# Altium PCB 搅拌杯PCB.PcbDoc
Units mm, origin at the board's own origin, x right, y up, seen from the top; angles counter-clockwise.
Board outline 36 x 32.5 mm, 2 copper layers (Top Layer, Bottom Layer); 74 components, 45 nets, 191 pads, 40 vias.
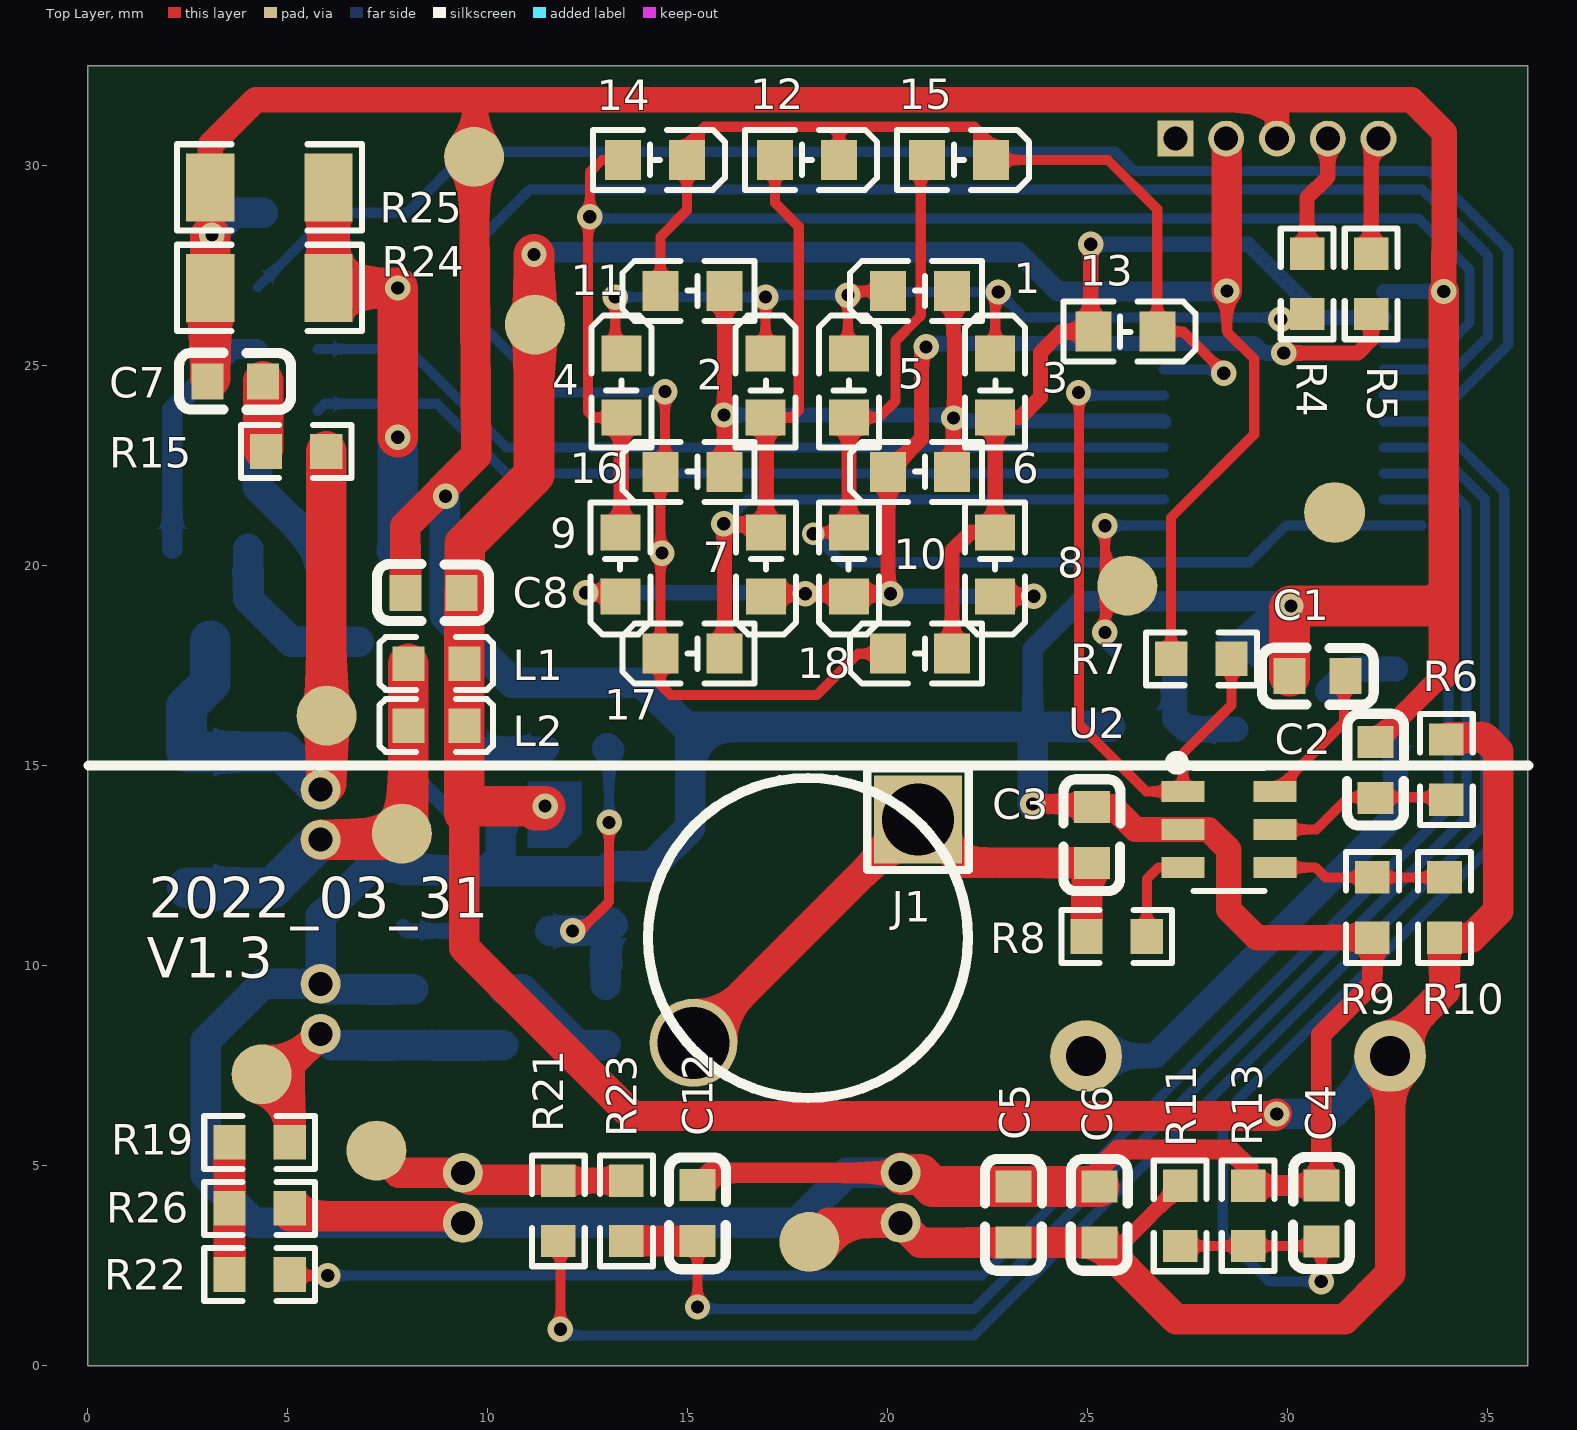
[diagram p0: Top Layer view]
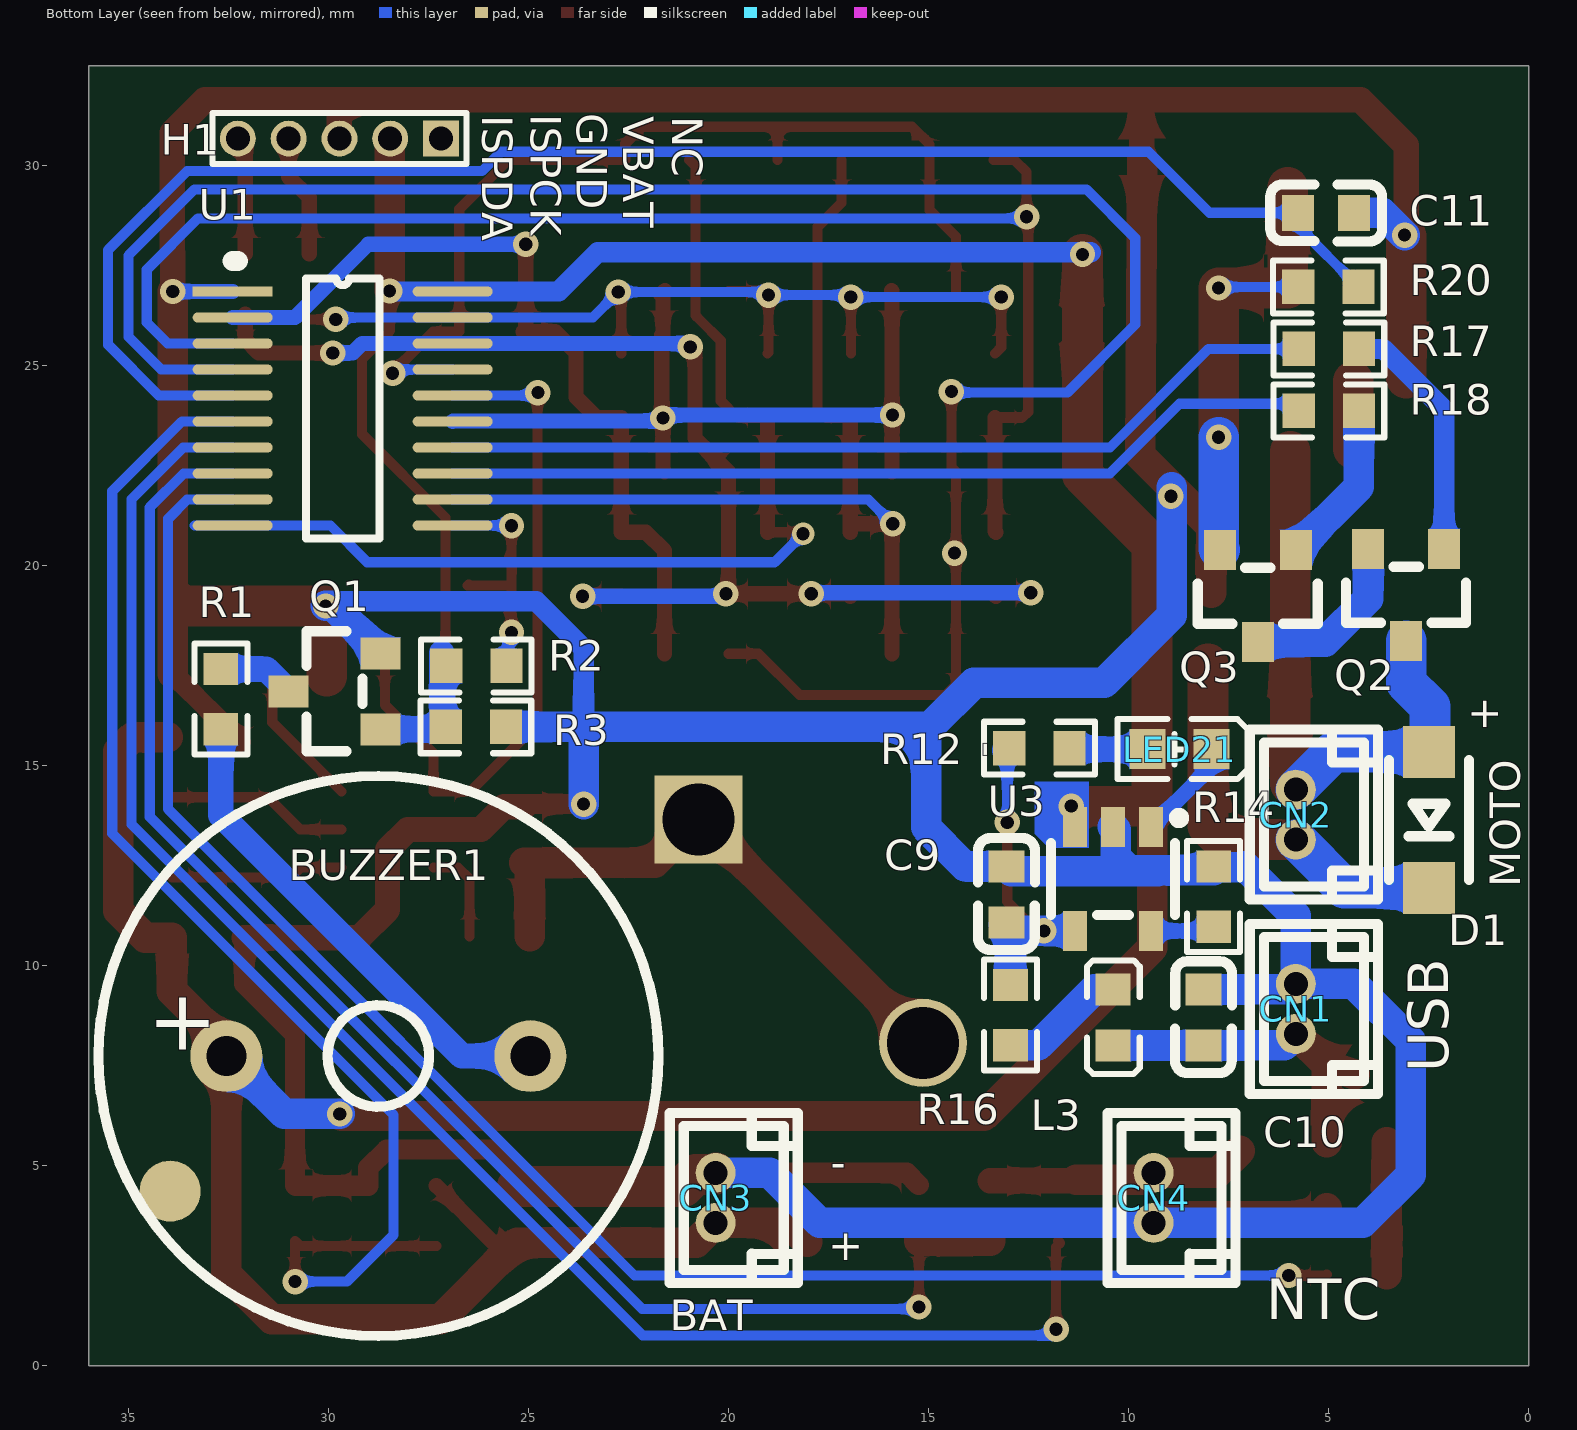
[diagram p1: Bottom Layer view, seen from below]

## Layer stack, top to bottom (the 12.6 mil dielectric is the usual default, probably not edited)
Top Solder: solder mask 0.0102, Solder Resist, Dk 3.5
Top Layer: signal copper 0.0356
Dielectric 1: dielectric 0.32, FR-4, Dk 4.8
Bottom Layer: signal copper 0.0356
Bottom Solder: solder mask 0.0102, Solder Resist, Dk 3.5

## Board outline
0,0 0,32.5 36,32.5 36,0

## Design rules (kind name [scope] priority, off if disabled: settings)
Clearance [All] p1: gap=0.203
ComponentClearance [All] p1 off: gap=0.254 collisioncheckmode=3 verticalgap=0.254 showdistances=FALSE
PolygonConnect [All] p1: connectstyle=Relief reliefconductorwidth=0.254 reliefentries=4 polygonreliefangle="90 Angle" airgapwidth=0.254
RoutingVias [All] p1: holewidth=0.711 width=1.27 viastyle="Through Hole" minholewidth=0.254 minwidth=0.254 maxholewidth=0.711 maxwidth=1.27
SolderMaskExpansion [All] p1: expansion=0.102
Width [All] p1: maxlimit=1.27 minlimit=0.203 preferedwidth=0.254
29 further rules are at their usual default settings.

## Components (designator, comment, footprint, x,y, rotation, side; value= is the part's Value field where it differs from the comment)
1 "LED-0603_W" LED0603-FD_WHITE 20.803,26.873 r180 top (schematic designator LED1)
2 "LED-0603_W" LED0603-FD_WHITE 16.942,24.511 r90 top (schematic designator LED2)
3 "LED-0603_W" LED0603-FD_WHITE 22.682,24.511 r90 top (schematic designator LED3)
4 "LED-0603_W" LED0603-FD_WHITE 13.335,24.511 r90 top (schematic designator LED4)
5 "LED-0603_W" LED0603-FD_WHITE 19.025,24.511 r90 top (schematic designator LED5)
6 "LED-0603_W" LED0603-FD_WHITE 20.803,22.352 r180 top (schematic designator LED6)
7 "LED-0603_W" LED0603-FD_WHITE 16.955,20.041 r270 top (schematic designator LED7)
8 "LED-0603_W" LED0603-FD_WHITE 22.682,20.041 r270 top (schematic designator LED8)
9 "LED-0603_W" LED0603-FD_WHITE 13.31,20.041 r270 top (schematic designator LED9)
10 "LED-0603_W" LED0603-FD_WHITE 19.025,20.041 r270 top (schematic designator LED10)
11 "LED-0603_W" LED0603-FD_WHITE 15.113,26.873 r180 top (schematic designator LED11)
12 "LED-0603_W" LED0603-FD_WHITE 17.977,30.15 r0 top (schematic designator LED12)
13 "LED-0603_W" LED0603-FD_WHITE 25.933,25.857 r0 top (schematic designator LED13)
14 "LED-0603_W" LED0603-FD_WHITE 14.173,30.15 r0 top (schematic designator LED14)
15 "LED-0603_W" LED0603-FD_WHITE 21.781,30.15 r0 top (schematic designator LED15)
16 "LED-0603_W" LED0603-FD_WHITE 15.113,22.352 r180 top (schematic designator LED16)
17 "LED-0603_W" LED0603-FD_WHITE 15.113,17.805 r180 top (schematic designator LED17)
18 "LED-0603_W" LED0603-FD_WHITE 20.803,17.805 r180 top (schematic designator LED18)
BUZZER1 "FMQ-BUZZER2" BUZ-TH_BD12.0-P7.60-D0.6-FD 28.753,7.747 r180 bottom
C1 "4.7nF" C0603 30.74,17.245 r180 top
C2 "0.1u" C0603 32.188,14.898 r270 top
C3 "nc" C0603 25.101,13.276 r90 top
C4 "0.1u" C0603 30.836,3.816 r270 top
C5 "1uF" C0603 23.139,3.785 r90 top
C6 "0.1u" C0603 25.286,3.785 r90 top
C7 "0.1u" C0603 3.683,24.613 r0 top
C8 "10uF" C0603 8.636,19.329 r0 top
C9 "4.7uF" C0603 13.056,11.791 r270 bottom
C10 "10uF" C0603 8.128,8.712 r270 bottom
C11 "0.1u" C0603 5.066,28.829 r0 bottom
C12 "0.1u" C0603 15.24,3.821 r90 top
CN1 "0530470210" CONN-TH_0530470210 5.817,8.925 r90 bottom
CN2 "0530470210" CONN-TH_0530470210 5.817,13.782 r90 bottom
CN3 "0530470210" CONN-TH_0530470210 20.32,4.201 r90 bottom
CN4 "0530470210" CONN-TH_0530470210 9.373,4.201 r90 bottom
D1 "1N4148W" SOD-123FL_L2.6-W1.6-LS3.4-RD 2.489,13.648 r270 bottom
H1 "HDR-F-2.54_1x5" 1.27mm_5PIN 27.187,30.683 r0 bottom
J1 "HDR-M-2.54_1x1" HDR-M-2.54_1X1 20.752,13.665 r0 top
L1 "22uH" L0603 8.712,17.551 r0 top
L2 "22uH" L0603 8.712,16.001 r0 top
L3 "BEAD" L0603 10.389,8.712 r270 bottom
LED21 "LED-0603_W" LED0603-FD_WHITE 8.725,15.418 r180 bottom
Q1 "2N7002" SOT-23_L2.9-W1.3-P0.95-LS2.4-BR 29.847,16.866 r180 bottom
Q2 "2N7002" SOT-23_L2.9-W1.3-P0.95-LS2.4-BR 3.059,19.279 r90 bottom
Q3 "2N7002" SOT-23_L2.9-W1.3-P0.95-LS2.4-BR 6.767,19.253 r90 bottom
R1 "50R" R0603 32.69,16.671 r90 bottom
R2 "1K" R0603 26.306,17.501 r180 bottom
R3 "100K" R0603 26.316,15.977 r180 bottom
R4 "100R" R0603 30.48,27.051 r270 top
R5 "100R" R0603 32.08,27.051 r270 top
R6 "0R" R0603 33.96,14.91 r90 top
R7 "10K" R0603 27.838,17.678 r180 top
R8 "1K" R0603 25.72,10.736 r180 top
R9 "NC" R0603 32.112,11.461 r90 top
R10 "NC" R0603 33.915,11.461 r90 top
R11 "3M" R0603 27.305,3.751 r90 top
R12 "1k" R0603 12.226,15.443 r180 bottom
R13 "1M" R0603 29.007,3.754 r270 top
R14 "1k" R0603 7.874,11.735 r90 bottom
R15 "1k" R0603 5.207,22.86 r0 top
R16 "0R" R0603 12.95,8.772 r270 bottom
R17 "100R" R0603 4.992,25.425 r180 bottom
R18 "100R" R0603 4.992,23.876 r180 bottom
R19 "1k" R0603 4.293,5.588 r0 top
R20 "1k" R0603 5.004,26.975 r180 bottom
R21 "200K" R0603 11.76,3.877 r90 top
R22 "1k" R0603 4.293,2.286 r0 top
R23 "1k" R0603 13.462,3.877 r270 top
R24 "1R" R1206 4.538,26.949 r0 top
R25 "1R" R1206 4.538,29.464 r0 top
R26 "100K" R0603 4.293,3.937 r0 top
U1 "ES7P0693FHTF" TSOP20 32.395,26.862 r180 bottom
U2 "AS01C(AI01)" SOT-23-6_L2.9-W1.6-P0.95-LS2.8-BL 28.527,13.411 r270 top
U3 "HE4054B" SOT-23-5_L3.0-W1.7-P0.95-LS2.8-BR 10.389,12.175 r90 bottom

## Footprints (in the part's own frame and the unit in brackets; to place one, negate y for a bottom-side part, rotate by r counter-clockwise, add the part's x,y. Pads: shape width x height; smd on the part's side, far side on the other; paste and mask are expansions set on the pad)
1.27mm_5PIN [mm]
  rect 0.9x0.9 hole 0.6: 1(0,0)
  round 0.9 hole 0.6: 2(1.27,0) 3(2.54,0) 4(3.81,0) 5(5.08,0)
  silkscreen extent -0.64,-0.64 5.71,0.64
BUZ-TH_BD12.0-P7.60-D0.6-FD [mm]
  round 1.8 hole 1: 1(-3.8,0) 2(3.8,0)
  silkscreen extent -7,-7 7,7
C0603 [mm]
  rect 0.8x0.9 smd: 1(-0.7,0) 2(0.7,0)
  silkscreen extent -1.41,-0.71 1.39,0.72
CONN-TH_0530470210 [mm]
  round 1 hole 0.6: 1(-0.625,0) 2(0.625,0)
  silkscreen extent -2.13,-2.05 2.13,1.15
HDR-M-2.54_1X1 [mm]
  rect 2.2x2.2 hole 1.8: 1(0,0)
  silkscreen extent -1.27,-1.27 1.27,1.27
L0603 [mm]
  rect 0.8x0.864 smd: 1(-0.7,0) 2(0.7,0)
  silkscreen extent -1.42,-0.65 1.41,0.67
LED0603-FD_WHITE [mm]
  rect 0.9x1 smd: 1(-0.8,0) 2(0.8,0)
  silkscreen extent -1.55,-0.75 1.75,0.75
R0603 [mm]
  rect 0.806x0.864 smd: 1(-0.753,0) 2(0.753,0)
  silkscreen extent -1.39,-0.66 1.39,0.66
R1206 [mm]
  rect 1.208x1.701 smd: 1(-1.479,0) 2(1.479,0)
  silkscreen extent -2.31,-1.08 2.31,1.08
SOD-123FL_L2.6-W1.6-LS3.4-RD [mm]
  rect 1.3x1.3 smd: 1(1.7,0) 2(-1.7,0)
  silkscreen extent -1.5,-1 1.5,1
SOT-23-5_L3.0-W1.7-P0.95-LS2.8-BR [mm]
  rect 1x0.6 smd: 1(1.3,-0.95) 2(1.3,0) 3(1.3,0.95) 4(-1.3,0.95) 5(-1.3,-0.95)
  silkscreen extent -0.9,-1.78 1.65,1.55
SOT-23-6_L2.9-W1.6-P0.95-LS2.8-BL [mm]
  rect 0.532x1.072 smd: 1(-0.95,-1.149) 2(0,-1.149) 3(0.95,-1.149) 4(0.95,1.149) 5(0,1.149) 6(-0.95,1.149)
  silkscreen extent -1.82,-1.45 1.54,0.89
SOT-23_L2.9-W1.3-P0.95-LS2.4-BR [mm]
  rect 1x0.8 smd: 1(1.15,-0.95) 2(1.15,0.95) 3(-1.15,0)
  silkscreen extent -0.7,-1.5 0.7,1.5
TSOP20 [mm]
  rect 2x0.25 smd: 1(0,0)
  oval 2x0.25 smd: 2(0,-0.65) 3(0,-1.3) 4(0,-1.95) 5(0,-2.6) 6(0,-3.25) 7(0,-3.9) 8(0,-4.55) 9(0,-5.2) 10(0,-5.85) 11(5.5,-5.85) 12(5.5,-5.2) 13(5.5,-4.55) 14(5.5,-3.9) 15(5.5,-3.25) 16(5.5,-2.6) 17(5.5,-1.95) 18(5.5,-1.3) 19(5.5,-0.65) 20(5.5,0)
  silkscreen extent 0,-6.18 3.66,0.76

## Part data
L3: library part 22uH
R1: library part 100R
R3: library part 1K
R6 R7 R16: library part NC
R11: library part 430k
R13: library part 430K
R21 R26: library part 33K

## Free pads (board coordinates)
  round 2.2 hole 1.8: 0(15.138,8.077)
  round 1.5 smd: 2(4.343,7.29) 2(5.969,16.256) 2(7.214,5.385) 2(7.849,13.31) 2(9.652,30.226) 2(11.176,26.035) 2(18.034,3.099) 2(25.984,19.507)
  round 1.524 smd: 3(31.166,21.336)
  round 2.54 on Top Solder: 3(31.166,21.336)
  round 1.524 smd far side: 3(33.96,4.369)
  round 2.54 on Bottom Solder: 3(33.96,4.369)

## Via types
v1: diameter 0.635, hole 0.33, Top Layer to Bottom Layer, tented both sides, 39 vias
v2: diameter 0.559, hole 0.33, Top Layer to Bottom Layer, 1 vias

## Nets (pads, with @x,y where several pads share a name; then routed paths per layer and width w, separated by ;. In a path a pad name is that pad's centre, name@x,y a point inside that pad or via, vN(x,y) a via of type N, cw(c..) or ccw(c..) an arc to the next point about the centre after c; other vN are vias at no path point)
BUZZER: pad.2@25.984,19.507 R2.2 U1.11 | length 5.9
  Top Layer w0.254: v1(25.425,18.339) pad.2@25.425,19.482 ; v1(25.425,21.006) pad.2@25.425,19.482 ; pad.2@26.492,19.533 26.518,19.507 25.984,19.507 25.451,19.507 pad.2@25.425,19.482
  Bottom Layer w0.254: v1(25.425,18.339) 25.425,18.07 R2.2@25.664,17.831 ; v1(25.425,21.006) 25.431,21.011 U1.11
GND: C1.2 C2.1 C3.2 C4.1 C5.2 C6.2 C7.1 C8.1 C9.1 C10.1 C11.1 C12.2 CN1.2 CN3.2 CN4.1 H1.3 pad.2@9.652,30.226 Q1.2 R3.2 R9.1 R13.1 R14.2 R24.1 R25.1 R26.2 U1.1 U2.2 U3.2 | length 192.5
  Top Layer w0.508: C12.2 15.545,4.826 CN3.2 ; v1(23.622,14.046) 25.031,14.046 C3.2 ; C6.2 25.286,4.94 25.756,5.41 28.55,5.41 29.007,4.953 R13.1 30.827,4.507 C4.1 30.836,8.28 32.112,9.556 R9.1 ; C2.1 33.895,17.306
  Top Layer w0.635: C7.1 C7.1@3.059,24.689 ; v1@3.059,28.27 R25.1 3.059,30.516 4.197,31.654 9.693,31.654 ; pad.2@9.652,30.226 9.693,31.591 9.693,31.598 9.693,31.654 ; C3.2 25.622,13.976 26.187,13.411 U2.2 28.016,13.411 28.524,12.903 28.524,11.405 29.221,10.708 R9.1 ; H1.3@29.727,30.836 29.727,31.267 29.34,31.654 ; 33.909,27.661 33.909,30.836 33.091,31.654 29.34,31.654 ; 9.693,31.654 29.34,31.654
  Top Layer w0.762: R26.2 5.046,3.742 9.092,3.742 9.258,3.576 CN4.1 ; C8.1 7.936,20.992 9.703,22.758 pad.2@9.652,30.226 ; 33.757,19.101 33.895,19.101 ; 33.895,17.306 33.895,19.101 ; v1(33.895,26.862) 33.895,19.101
  Top Layer w1.016: C7.1@3.059,24.689 R24.1 v1@3.059,28.245 ; CN3.2 20.359,4.787 20.822,4.787 21.124,4.485 C6.2 ; C1.2 30.04,18.966 v1(30.074,18.999) 33.655,18.999 33.757,19.101
  Bottom Layer w0.381: U1.1 v1(33.895,26.862)
  Bottom Layer w0.508: 23.622,16.104 23.622,17.932 24.803,19.113 29.959,19.113 v1(30.074,18.999)
  Bottom Layer w0.762: v1(3.099,28.27) 3.658,28.829 C11.1 ; R14.2 R14.2@7.874,12.471 ; C10.1 5.955,9.412 CN1.2 ; v1@8.915,21.971 8.915,18.771 10.612,17.074 13.863,17.074 14.96,15.977 15.062,15.977 ; 9.267,12.37 12.935,12.37 C9.1 14.091,12.49 15.062,13.462 15.062,15.977 ; U3.2 10.323,13.409 10.323,12.733 9.981,12.391 7.874,12.391 R14.2@7.874,12.471 ; CN3.2 18.974,4.826 17.724,3.576 CN4.1 4.146,3.576 2.946,4.775 2.946,8.128 4.369,9.55 CN1.2 ; v1(23.622,14.046) 23.622,15.977 ; 23.622,16.104 23.749,15.977 ; R3.2 23.749,15.977 ; Q1.2 29.88,18.999 v1(30.074,18.999) ; CN1.2 5.817,11.252 5.842,11.252 7.078,12.488 7.078,12.471 R14.2@7.874,12.471 ; 15.062,15.977 23.622,15.977 ; 23.622,15.977 23.749,15.977
  other v1: 8.941,21.742
IO_OUT: R21.1 U1.7 | length 41.9
  Top Layer w0.254: R21.1 11.709,3.073 11.811,2.971 v1(11.811,0.914)
  Bottom Layer w0.254: v1(11.811,0.914) 11.963,0.762 22.147,0.762 34.925,13.54 34.925,21.666 33.63,22.962 U1.7
ISPCK: H1.4 R4.1 | length 3.2
  Top Layer w0.381: R4.1 30.48,29.21 30.997,29.727 H1.4 H1.4@30.997,30.836
ISPDA: H1.5 R5.1 | length 3.1
  Top Layer w0.381: R5.1 32.08,30.649 H1.5@32.267,30.836
LED_IO_0: 1.2 2.2 3.2 4.2 5.2 R4.2 U1.19 | length 24.9
  Top Layer w0.254: v1(13.183,26.721) 13.183,25.463 4.2 ; 2.2 v1(16.942,26.721) ; 5.2 18.999,25.336 v1(18.999,26.772) 19.101,26.873 1.2 ; 3.2 22.682,26.772 v1(22.758,26.848) ; v1(29.82,26.162) 30.556,26.162 R4.2@30.605,26.212
  Bottom Layer w0.254: v1(13.183,26.721) v1(16.942,26.721) 16.992,26.772 v1(18.999,26.772) 18.923,26.848 v1(22.758,26.848) 23.395,26.212 U1.19 29.77,26.212 v1(29.82,26.162)
LED_IO_1: 6.2 7.2 8.2 9.2 10.2 R5.2 U1.18 | length 32.9
  Top Layer w0.381: v1(12.446,19.329) 13.348,19.329 13.373,19.304 9.2 ; 7.2 17.019,19.304 v1(17.932,19.304) v1@20.003,19.304 ; 6.2 v1@20.003,19.304 ; 6.2@20.041,22.39 20.841,23.19 20.841,25.387 20.879,25.349 20.98,25.451 v1(20.955,25.476) ; v1(20.066,19.304) v1@20.003,19.304 ; 8.2 v1(23.647,19.241) ; v1(29.896,25.324) 31.75,25.324 32.08,25.654 R5.2
  Bottom Layer w0.381: v1(12.446,19.329) 17.907,19.329 v1(17.932,19.304) ; v1(20.066,19.304) 20.129,19.241 v1(23.647,19.241) ; v1@20.913,25.478 20.937,25.502 20.955,25.483 v1(20.955,25.476) 21.04,25.562 U1.18 29.159,25.562 29.397,25.324 v1(29.896,25.324)
LED_IO_2: 11.2 12.2 13.2 14.2 15.2 U1.17 | length 24.5
  Top Layer w0.254: 11.2 14.313,28.232 14.973,28.892 14.2 14.973,30.535 15.418,30.98 18.777,30.98 ; 12.2 18.777,30.98 ; v1(28.397,24.816) 28.397,24.841 27.381,25.857 13.2 26.733,28.918 25.502,30.15 15.2 22.581,30.556 22.157,30.98 18.777,30.98
  Bottom Layer w0.254: U1.17 v1@28.397,24.912
LED_IO_3: 16.2 17.2 18.2 U1.4 | length 52.3
  Top Layer w0.254: v1(14.427,24.359) 14.427,22.466 16.2 17.2 14.313,17.03 14.568,16.775 18.223,16.775 19.253,17.805 18.2
  Bottom Layer w0.254: v1@14.173,24.333 11.532,24.333 9.83,26.035 9.83,28.194 11.049,29.413 33.35,29.413 35,27.763 35,25.729 34.183,24.912 U1.4 ; v1@14.326,20.32 v1(14.351,20.32) v1@14.427,20.396
LED_IO_4: 1.1 6.1 11.1 16.1 U1.15 | length 20.5
  Top Layer w0.381: 16.1 11.1 11.1@15.926,26.886 ; 1.1@21.59,26.886 1.1 21.692,26.784 21.641,26.733 21.641,25.796 21.666,25.771 21.666,23.724 v1(21.641,23.698) ; 6.1 21.641,22.39 v1(21.641,23.698) ; v1@21.641,23.749 v1(21.641,23.698)
  Bottom Layer w0.381: v1(15.9,23.774) v1@21.641,23.774 ; v1(21.641,23.698) v1@21.641,23.774 ; U1.15 26.885,23.622 21.615,23.622 21.565,23.673 21.565,23.698 v1@21.641,23.774
LED_IO_5: 2.1 7.1 12.1 17.1 U1.12 | length 25.6
  Top Layer w0.254: 2.1 17.59,23.711 17.772,23.893 17.772,28.481 17.177,29.077 12.1
  Top Layer w0.381: v1(15.896,21.052) v1@15.913,21.052 ; 17.1 v1@15.913,21.052 ; 7.1@16.744,21.052 v1@15.913,21.052 ; 2.1 16.955,23.697 7.1
  Bottom Layer w0.254: v1(15.896,21.052) 16.505,21.662 U1.12
LED_IO_6: 3.1 8.1 13.1 18.1 U1.2 | length 21
  Top Layer w0.381: 18.1 21.603,20.383 22.06,20.841 8.1 3.1 23.305,23.711 23.812,24.219 23.812,25.336 24.333,25.857 13.1@25.07,25.857 ; v1(25.07,28.042) 13.1@25.07,25.857 ; 13.1 13.1@25.07,25.857
  Bottom Layer w0.381: v1(25.07,28.042) 29.007,28.042 30.837,26.212 U1.2
LED_IO_7: 4.1 9.1 14.1 U1.3 | length 37.1
  Top Layer w0.254: 4.1 12.649,23.711 12.505,23.855 12.505,28.685 v1(12.548,28.727) 12.548,29.845 12.852,30.15 14.1
  Top Layer w0.381: 9.1 13.335,20.866 4.1
  Bottom Layer w0.254: v1@12.446,28.702 12.471,28.727 v1(12.548,28.727) ; v1@12.53,28.778 12.548,28.761 v1(12.548,28.727) ; U1.3 34.02,25.562 34.543,26.085 34.543,27.408 33.261,28.689 12.586,28.689 v1(12.548,28.727)
LED_IO_8: 5.1 10.1 15.1 U1.10 | length 27.3
  Top Layer w0.254: v2(18.136,20.803) 18.174,20.841 10.1 ; 5.1 19.774,23.711 20.193,24.13 20.193,25.63 20.712,26.149 20.714,26.149 20.823,26.258 20.823,29.992 15.1
  Top Layer w0.381: 10.1 5.1
  Bottom Layer w0.254: v2(18.136,20.803) 18.847,20.091 29.032,20.091 29.952,21.011 U1.10 U1.10@33.345,21.011
MOTO_CONTROL_A: R17.1 U1.14 | length 22.2
  Bottom Layer w0.254: R17.1 8.001,25.425 10.465,22.962 U1.14
MOTO_CONTROL_B: R18.1 U1.13 | length 21.9
  Bottom Layer w0.254: R18.1 5.923,24.054 8.726,24.054 10.468,22.312 U1.13
MOTO_CURRERN: C11.2 R20.2 U1.5 | length 39.9
  Bottom Layer w0.254: R20.2 5.766,28.49 C11.2 7.976,28.829 9.5,30.353 25.679,30.353 26.162,29.87 33.54,29.87 35.509,27.901 35.509,25.527 34.244,24.262 U1.5
NetBUZZER1_2: BUZZER1.2 R1.1 | length 12.4
  Bottom Layer w0.635: BUZZER1.2 26.67,7.747 32.69,13.767 R1.1
NetC1_1: C1.1 U2.6 | length 3.6
  Top Layer w0.254: U2.6 31.408,16.093 31.408,17.245 C1.1
NetC2_2: C2.2 R6.1 U2.5 | length 4.7
  Top Layer w0.254: U2.5 30.709,13.411 31.514,14.216 R6.1@34.017,14.216
NetC3_1: C3.1 J1.1 pad.0 R8.2 | length 14.6
  Top Layer w0.762: pad.0 J1.1@20.726,13.665 ; J1.1 21.841,12.576 C3.1 24.966,12.442 R8.2
NetC7_2: C7.2 R15.1 | length 1.8
  Top Layer w0.762: R15.1@4.383,22.931 R15.1
  Top Layer w1.016: R15.1@4.383,22.931 C7.2
NetC9_2: C9.2 R12.1 R16.1 U3.4 | length 8.4
  Top Layer w0.254: v1(12.116,10.875) 12.298,10.875 13.03,11.608 v1(13.03,13.589)
  Bottom Layer w0.254: v1(13.03,13.589) R12.1@13.03,15.392
  Bottom Layer w0.762: U3.4@11.557,10.875 v1(12.116,10.875) 12.84,10.875 C9.2@12.95,10.985 ; R16.1 C9.2@12.95,10.985 ; R12.1 R12.1@13.03,15.392 ; C9.2@12.95,10.985 C9.2@12.989,11.024 ; C9.2@12.989,11.024 13.123,11.024 C9.2 C9.2@12.989,11.024
NetCN2_1: CN2.1 D1.1 L1.1 L2.1 pad.2@7.849,13.31 | length 10.2
  Top Layer w1.016: CN2.1 7.671,13.157 8.012,13.499 L2.1 L1.1
  Bottom Layer w1.016: D1.1 4.608,11.948 CN2.1
NetCN2_2: CN2.2 D1.2 pad.2@5.969,16.256 Q2.3 R15.2 | length 15.3
  Top Layer w0.762: CN2.2 CN2.2@5.96,14.551
  Top Layer w1.016: CN2.2@5.96,14.551 R15.2
  Bottom Layer w1.016: Q2.3 3.059,17.08 2.464,16.485 2.464,15.374 D1.2 4.876,15.348 CN2.2
NetCN4_2: CN4.2 pad.2@7.214,5.385 R21.2 R23.1 | length 6.6
  Top Layer w0.635: 11.303,4.66 11.333,4.63 R21.2 R23.1
  Top Layer w0.762: pad.2@7.214,5.385 7.772,4.826 CN4.2 9.539,4.66 11.303,4.66
NetL3_1: L3.1 R16.2 | length 3.1
  Bottom Layer w0.762: L3.1 10.857,9.412 12.251,8.019 R16.2
NetLED21_1: LED21.1 R12.2 | length 2
  Bottom Layer w0.635: LED21.1 11.448,15.418 R12.2
NetLED21_2: LED21.2 U3.1 | length 2.6
  Bottom Layer w0.381: LED21.2 7.925,14.989 U3.1
NetQ1_1: Q1.1 R2.1 R3.1 | length 3.3
  Bottom Layer w0.635: R2.1@27.171,17.831 27.171,16.18 27.435,15.916 Q1.1
NetQ1_3: Q1.3 R1.2 | length 1.9
  Bottom Layer w0.635: Q1.3 31.555,17.424 R1.2
NetQ2_1: Q2.1 R17.2 | length 6.2
  Bottom Layer w0.508: Q2.1 2.109,23.902 3.632,25.425 R17.2
NetQ2_2: Q2.2 Q3.3 | length 4.5
  Bottom Layer w0.762: Q2.2 4.009,19.181 5.087,18.103 Q3.3
NetQ3_1: Q3.1 R18.2 | length 4.1
  Bottom Layer w0.762: R18.2 4.239,21.981 Q3.1
NetQ3_2: Q3.2 R20.1 R24.2 R25.2 | length 12.8
  Top Layer w1.016: R25.2 R24.2 v1(7.747,26.949) v1(7.747,23.216)
  Bottom Layer w0.254: R20.1 7.722,26.975 v1(7.747,26.949)
  Bottom Layer w1.016: Q3.2 7.747,20.433 v1(7.747,23.216)
NetR8_1: R8.1 U2.3 | length 2.5
  Top Layer w0.254: R8.1 26.473,12.173 26.761,12.461 U2.3
NetR9_2: R9.2 R10.2 U2.4 | length 4.3
  Top Layer w0.254: U2.4 30.693,12.461 30.941,12.214 R9.2 R10.2
NetR14_1: R14.1 U3.5 | length 1.6
  Bottom Layer w0.381: R14.1 7.98,10.875 U3.5
NetR19_1: R19.1 R22.1 R26.1 | length 3.3
  Top Layer w0.762: R22.1 R26.1 R19.1
NTC_IN: C12.1 R23.2 U1.8 | length 38.1
  Top Layer w0.254: C12.1@15.238,3.124 C12.1 v1(15.24,1.473)
  Top Layer w0.762: R23.2 C12.1@15.238,3.124
  Bottom Layer w0.254: v1(15.24,1.473) 15.24,1.626 15.443,1.422 22.16,1.422 34.468,13.73 34.468,21.463 33.619,22.312 U1.8
TOUCH_IN: R7.1 U1.16 U2.1 | length 17.7
  Top Layer w0.254: v1(24.765,24.333) 24.765,24.384 24.778,24.397 24.778,16.04 26.457,14.361 U2.1 27.378,15.313 28.592,16.527 R7.1
  Bottom Layer w0.254: v1(24.765,24.333) 24.841,24.257 26.891,24.257 U1.16
USB_CHECK: R22.2 U1.9 | length 42.9
  Top Layer w0.254: R22.2 5.071,2.261 v1(5.994,2.261)
  Bottom Layer w0.254: v1(5.994,2.261) 22.352,2.261 34.011,13.919 34.011,21.184 33.533,21.661 U1.9
USB_IN: C10.2 CN1.1 L3.2 pad.2@4.343,7.29 R19.2 | length 8.5
  Top Layer w0.762: pad.2@4.343,7.29 pad.2@5.046,7.529 ; R19.2 pad.2@5.046,7.529 ; CN1.1 pad.2@5.046,7.529
  Bottom Layer w0.762: CN1.1 6.105,8.012 C10.2 L3.2
VBAT: BUZZER1.1 C5.1 C6.1 C8.2 CN3.1 H1.2 L1.2 L2.2 pad.2@11.176,26.035 pad.2@18.034,3.099 R6.2 R7.2 R10.1 R11.2 U1.20 U3.3 | length 114.2
  Top Layer w0.254: R7.2 27.076,17.687 27.076,21.209 29.159,23.292 29.159,25.171 28.473,25.857 v1(28.473,26.873)
  Top Layer w0.381: C6.1 25.885,3.085 R11.2
  Top Layer w0.762: 9.412,13.818 9.412,10.451 13.614,6.248 29.667,6.248 v1(29.718,6.299) ; pad.2@18.034,3.099 18.511,3.576 CN3.1 20.811,3.085 C6.1 27.202,1.168 31.42,1.168 32.553,2.301 BUZZER1.1 32.553,8.01 33.915,9.373 R10.1 34.584,10.708 35.255,11.379 35.255,15.367 34.9,15.723 R6.2@34.017,15.723 ; v1(28.473,26.873) H1.2@28.473,30.683
  Top Layer w1.016: C8.2@9.412,19.329 L1.2 L2.2 9.412,13.818 9.59,13.995 v1(11.43,13.995) ; C8.2@9.423,19.075 9.423,20.549 11.151,22.276 v1(11.151,27.788) ; v1@11.201,13.89 v1@11.379,13.89
  Bottom Layer w0.508: v1@10.947,27.838 23.266,27.838 24.243,26.862 U1.20 28.462,26.862 v1(28.473,26.873) ; U3.3 11.339,14.361 11.425,14.275 11.379,14.229 11.43,14.178 v1(11.43,13.995)
  Bottom Layer w0.762: v1(29.718,6.299) 31.105,6.299 BUZZER1.1
VBAT_IN: C4.2 R11.1 R13.2 U1.6 | length 32.8
  Top Layer w0.254: R11.1 29.004,2.998 R13.2 30.72,3.001 C4.2 v1(30.836,2.108)
  Bottom Layer w0.254: v1(30.836,2.108) 29.54,2.108 28.372,3.277 28.372,6.274 35.408,13.31 35.408,21.869 33.665,23.612 U1.6
pads on no net: H1.1

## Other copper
Top Layer:
  rectangle net GND: 33.579,26.645 34.214,27.889
Bottom Layer:
  region net VBAT: 12.344,14.605 12.344,13.31 11.989,12.954 10.998,12.954 10.998,14.605

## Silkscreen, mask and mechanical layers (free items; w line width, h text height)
Top Overlay:
  circle w0.254: c18,10.701 r4
  lines w0.254: 0.015,15.014 36.015,15.014
  text "2022_03_31" at 1.524,11.201 h1.02
  text "V1.3" at 1.473,9.703 h1.02
Bottom Overlay:
  text "GND" at 23.8,31.318 h0.76 r90
  text "ISPCK" at 24.943,31.293 h0.76 r90
  text "ISPDA" at 26.162,31.267 h0.76 r90
  text "NC" at 21.412,31.242 h0.76 r90
  text "VBAT" at 22.631,31.242 h0.76 r90
  text "+" at 0.762,15.85 h0.76 r270
  text "-" at 13.284,15.215 h0.76 r270
  text "MOTO" at 0.203,11.963 h0.76 r270
  text "USB" at 2.007,7.341 h1.02 r270
  text "-" at 17.45,4.699 h0.76
  text "+" at 17.501,2.642 h0.76
  text "NTC" at 6.553,1.168 h1.02
  text "BAT" at 21.463,0.889 h0.76
Mechanical 1:
  the board outline again, w0.254
Drill Drawing:
  lines w0.254: 21.539,20.295 28.092,29.388 ; 24.181,29.388 25.502,20.269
